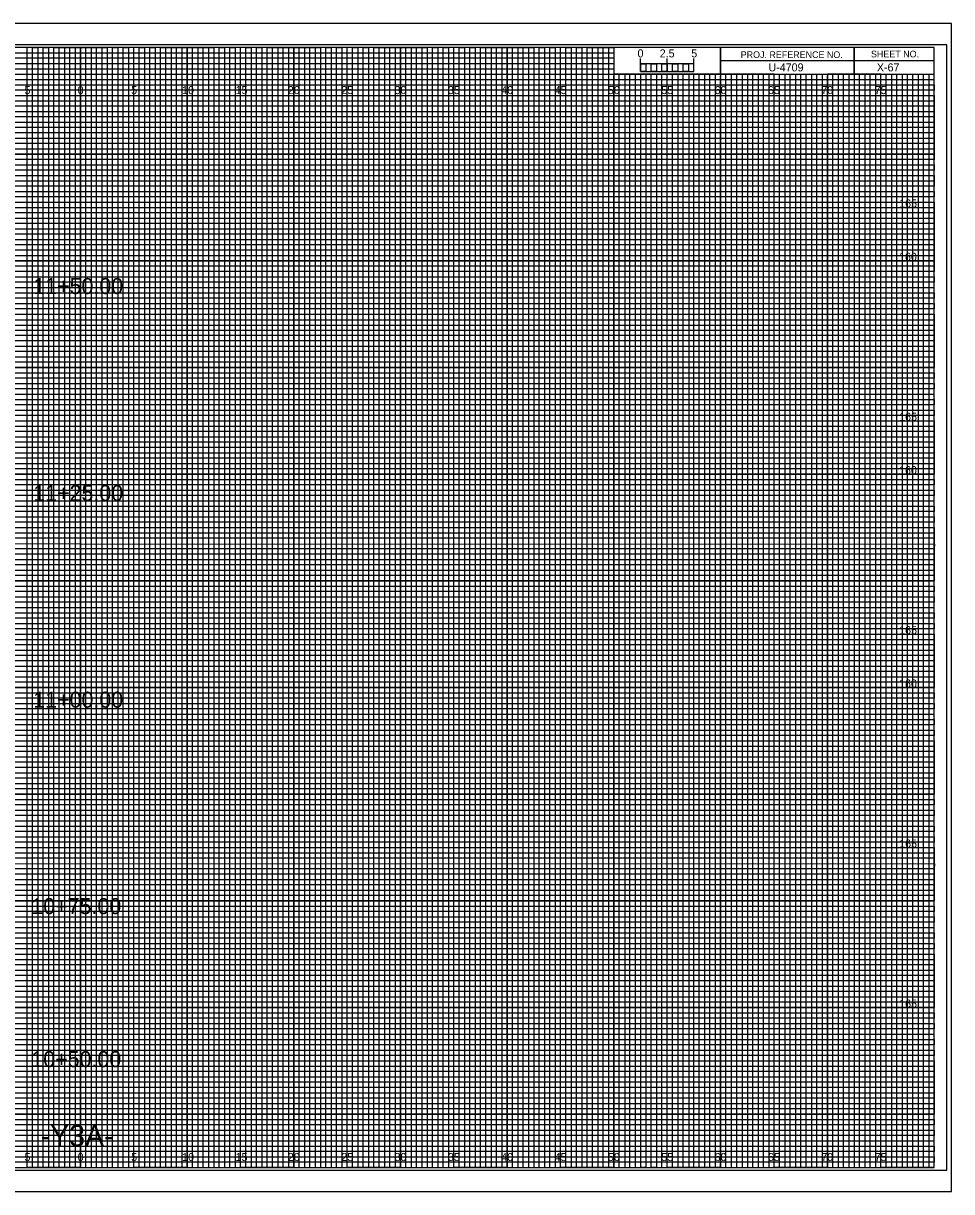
# Model space of a CAD drawing. Extents: x -7 to 162, y -2 to 107.
# Drawn here: x 74.6 to 161.7, y -2.3 to 107.3 of the extents above; entities that cross this region are included whole.
import ezdxf

# ---------------------------------------------------------------- set-up
doc = ezdxf.new("R2010")
doc.units = 0
for name, color, linetype in [('Prop CMT Slope Grass', 7, 'Continuous'), ('Prop XS Alignment Label', 7, 'Continuous'), ('Prop XS Bar Scale Labels', 7, 'Continuous'), ('Prop XS Earthwork Shape', 7, 'Continuous'), ('Prop XS Elevation Labels', 7, 'Continuous'), ('Prop XS Hydro Elevations', 7, 'Continuous'), ('Prop XS Project Number', 7, 'Continuous'), ('Prop XS SE Text', 7, 'Continuous'), ('Prop XS Sheet Number', 7, 'Continuous'), ('Prop XS Side Slope Text', 7, 'Continuous'), ('Prop XS Station Labels', 7, 'Continuous'), ('Sheet Cross Section Grid Minor 2 CELL', 7, 'Continuous'), ('Sheet Cross Section Scale CELL', 7, 'Continuous'), ('Sheet Cutting Line CELL', 7, 'Continuous'), ('Sheet DOT Grid CELL', 7, 'Continuous'), ('Sheet Plot Border Inside CELL', 7, 'Continuous'), ('Sheet Plot Border Outside CELL', 7, 'Continuous')]:
    doc.layers.add(name, color=color, linetype=linetype)

msp = doc.modelspace()

# ---------------------------------------------------------------- linework, layer by layer
at = {"layer": 'Prop XS Earthwork Shape'}
for p, q in [((152.5, 105), (152.5, 102.5)), ((152.5, 102.5), (152.5, 105)), ((160, 103.75), (140, 103.75)), ((140, 103.75), (140, 102.5)), ((140, 102.5), (160, 102.5))]:
    msp.add_line(p, q, dxfattribs=at)
for points in [[(160, 105), (0, 105), (0, 0), (160, 0)], [(140, 105), (130, 105), (130, 102.52), (140, 102.52)], [(160, 105), (140, 105), (140, 102.5), (160, 102.5)]]:
    msp.add_lwpolyline(points, close=True, dxfattribs=at)
at = {"layer": 'Prop XS Hydro Elevations'}
for p, q in [((0, 104.5), (130, 104.5)), ((130, 104.5), (130, 103.99)), ((130, 103.99), (0, 103.99)), ((0, 103.5), (130, 103.5)), ((130, 102.95), (0, 102.95)), ((130, 103.5), (130, 102.95)), ((0, 102), (160, 102))]:
    msp.add_line(p, q, dxfattribs=at)
for points in [[(0, 101.5), (135, 101.5), (160, 101.5), (160, 101), (0, 101)], [(0, 100.5), (160, 100.5), (160, 99.5), (0, 99.5)], [(0, 99), (160, 99), (160, 98.5), (0, 98.49)], [(0, 98), (160, 98), (160, 97), (0, 97)], [(0, 96.5), (160, 96.5), (160, 96), (0, 96)], [(0, 95.5), (160, 95.5), (160, 94.5), (0, 94.5)], [(0, 94), (160, 94), (160, 93.5), (0, 93.5)], [(0, 93), (160, 93), (160, 92), (0, 92)], [(0, 91.5), (160, 91.5), (160, 91), (0, 91)], [(0, 90.5), (160, 90.5), (160, 89.5), (0, 89.5)], [(0, 89), (160, 89), (160, 88.5), (0, 88.5)], [(0, 88), (160, 88), (160, 86.98), (160, 86.5), (160, 86), (0, 86)], [(0, 87), (160, 87), (160, 86.5), (0, 86.5)], [(0, 85.5), (160, 85.5), (160, 84.5), (0, 84.52)], [(0, 84.52), (160, 84.5), (160, 84), (0, 84)], [(0, 83.5), (160, 83.5), (160, 83), (0, 83)], [(0, 82), (160, 82), (160, 81.5), (0, 81.5)], [(0, 81), (160, 81), (160, 80.5), (0, 80.5)], [(-0.04, 79.45), (160, 79.45), (160, 78.94), (-0.04, 78.94)], [(0, 78.5), (160, 78.5), (160, 78), (0, 78)], [(0, 77), (160, 77), (160, 76.5), (0, 76.5)], [(0, 76), (160, 76), (160, 75.5), (0, 75.5)], [(0, 74.5), (160, 74.5), (160, 74), (0, 74)], [(0, 73.5), (160, 73.5), (160, 73), (0, 73)], [(0, 72), (160, 72), (160, 71.5), (0, 71.5)], [(0, 71), (160, 71), (160, 70.5), (0, 70.5)], [(0, 69.5), (160, 69.5), (160, 68.99), (0, 69)], [(0, 68.5), (160, 68.5), (160, 68), (0, 68)], [(0, 67), (160, 67), (160, 66.5), (0, 66.5)], [(0, 66), (160, 66), (160, 65.5), (0, 65.5)], [(0, 64.5), (160, 64.5), (160, 64), (0, 64)], [(0, 63.5), (160, 63.5), (160, 63), (0, 63)], [(0, 62), (160, 62), (160, 61.5), (0, 61.5)], [(0, 61), (160, 61), (160, 60.5), (0, 60.5)], [(0, 59.5), (160, 59.5), (160, 59), (0, 59)], [(0, 58.5), (160.03, 58.45), (160, 58), (0, 58)], [(0, 57), (160, 57), (160, 56.5), (0, 56.5)], [(0, 56), (160, 56), (160, 55.5), (0, 55.5)], [(0, 54.5), (160, 54.5), (160, 54), (0, 54)], [(0, 53.5), (160, 53.5), (160, 53), (0, 53)], [(0, 52), (160, 52), (160, 51.5), (0, 51.5)], [(0, 51), (160, 51), (160, 50.5), (0, 50.5)], [(0, 49.5), (160, 49.5), (160, 49), (0, 49)], [(0, 48.5), (160, 48.5), (160, 48), (0, 48)], [(0, 47), (160, 47), (160, 46.5), (0, 46.5)], [(0, 46), (160, 46), (160, 45.5), (0, 45.5)], [(0, 44.5), (160, 44.5), (160, 44), (0, 44)], [(0, 43.5), (160, 43.5), (160, 43), (0, 43)], [(0, 42), (160, 42), (160, 41.5), (0, 41.5)], [(0, 41), (160, 41), (160, 40.5), (0, 40.5)], [(0, 39.5), (160, 39.5), (160, 38.99), (0, 39)], [(0, 38.5), (160, 38.5), (160, 38), (0, 38)], [(0, 37), (160, 37), (160, 36.5), (0, 36.5)], [(0, 36), (160, 36), (160, 35.5), (0, 35.5)], [(0, 34.5), (160, 34.5), (160, 34), (0, 34)], [(0, 33.5), (160, 33.5), (160, 33), (0, 33)], [(0, 32), (160, 32), (160, 31.5), (0, 31.5)], [(0, 31), (160, 31), (160, 30.5), (0, 30.5)], [(0, 29.5), (160, 29.5), (160, 29), (0, 29)], [(0, 28.5), (160.03, 28.46), (160, 28), (0, 28)], [(0, 27), (160, 27), (160, 26.5), (0, 26.5)], [(0, 26), (160, 26), (160, 25.5), (0, 25.5)], [(0, 24.5), (160, 24.5), (160, 24), (0, 24)], [(0, 23.5), (160, 23.5), (160, 23), (0, 23)], [(0, 22), (160, 22), (160, 21.5), (0, 21.5)], [(0, 21), (160, 21), (160, 20.5), (0, 20.5)], [(0, 19.5), (160, 19.5), (160, 19), (0, 19)], [(0, 18.5), (160, 18.5), (160, 18), (0, 18)], [(0, 17), (160, 17), (160, 16.5), (0, 16.5)], [(0, 16), (160, 16), (160, 15.5), (0, 15.5)], [(0, 14.5), (160, 14.5), (160, 14), (0, 14)], [(0, 13.5), (160, 13.5), (160, 13), (0, 13)], [(0, 12), (160, 12), (160, 11.5), (0, 11.5)], [(0, 11), (160, 11), (160, 10.5), (0, 10.5)], [(0, 9.5), (160, 9.5), (160, 9), (0, 9)], [(0, 8.5), (160, 8.5), (160, 8), (0, 8)], [(0, 7), (160, 7), (160, 6.5), (0, 6.5)], [(0, 6), (160, 6), (160, 5.5), (0, 5.5)], [(0, 4.5), (160, 4.5), (160, 4), (0, 4)], [(0, 3.5), (160, 3.5), (160, 3), (0, 3)], [(0, 2), (160, 2), (160, 1.5), (0, 1.5)], [(0, 1), (160, 1), (160, 0.5), (0, 0.5)]]:
    msp.add_lwpolyline(points, dxfattribs=at)
at = {"layer": 'Prop XS SE Text'}
for p, q in [((75, 105), (70, 105)), ((75, 0), (75, 105)), ((85, 105), (80, 105)), ((80, 105), (80, 0)), ((85, 0), (85, 105)), ((95, 105), (90, 105)), ((90, 105), (90, 0)), ((95, 0), (95, 105)), ((105, 105), (100, 105)), ((100, 105), (100, 0)), ((105, 0), (105, 105)), ((115, 105), (110, 105)), ((110, 105), (110, 0)), ((115, 0), (115, 105)), ((125, 105), (120, 105)), ((120, 105), (120, 0)), ((125, 0), (125, 105)), ((130, 105), (130, 0)), ((135, 0), (135, 102.5)), ((145, 102.5), (140, 102.5)), ((140, 102.5), (140, 0)), ((145, 0), (145, 102.5)), ((155, 102.5), (150, 102.5)), ((150, 102.5), (150, 0)), ((155, 0), (155, 102.5)), ((80, 0), (75, 0)), ((90, 0), (85, 0)), ((100, 0), (95, 0)), ((110, 0), (105, 0)), ((120, 0), (115, 0)), ((130, 0), (125, 0)), ((140, 0), (135, 0)), ((150, 0), (145, 0)), ((160, 0), (155, 0)), ((160, 0), (160, 0))]:
    msp.add_line(p, q, dxfattribs=at)
for points in [[(0, 100), (160, 100), (160, 95), (0, 95)], [(0, 90), (160, 90), (160, 85), (0, 85)], [(0, 80), (160, 80), (160, 75), (0, 75)], [(0, 70), (160, 70), (160, 65), (0, 65)], [(0, 60), (160, 60), (160, 55), (0, 55)], [(0, 50), (160, 50), (160, 45), (0, 45)], [(0, 40), (160, 40), (160, 35), (0, 35)], [(0, 30), (160, 30), (160, 25), (0, 25)], [(0, 20), (160, 20), (160, 15), (0, 15)], [(0, 10), (160, 10), (160, 5), (0, 5)]]:
    msp.add_lwpolyline(points, dxfattribs=at)
at = {"layer": 'Prop XS Side Slope Text'}
for points in [[(72.5, 0), (77.5, 0), (77.5, 105), (82.5, 105), (82.5, 0), (87.5, 0), (87.5, 105), (92.5, 105), (92.5, 0), (97.5, 0), (97.5, 105), (102.5, 105), (102.5, 0), (107.5, 0), (107.5, 105), (112.5, 105), (112.5, 0), (117.5, 0), (117.5, 105), (122.5, 105), (122.5, 0), (127.5, 0), (127.5, 105), (129.97, 105), (130, 105), (130, 102.5), (132.5, 102.5), (132.5, 0), (137.5, 0), (137.5, 102.5), (142.5, 102.5), (142.5, 0), (147.5, 0), (147.5, 102.5), (152.5, 102.5), (152.5, 0), (157.5, 0), (157.5, 102.5)], [(0, 102.5), (137.5, 102.5)], [(0, 92.5), (160, 92.5), (160, 97.5), (0, 97.5)], [(0, 82.5), (160, 82.5), (160, 87.5), (0, 87.5)], [(0, 72.5), (160, 72.5), (160, 77.5), (0, 77.5)], [(0, 62.5), (160, 62.5), (160, 67.5), (0, 67.5)], [(0, 52.5), (160, 52.5), (160, 57.5), (0, 57.5)], [(0, 42.5), (160, 42.5), (160, 47.5), (0, 47.5)], [(0, 32.5), (160, 32.5), (160, 37.5), (0, 37.5)], [(0, 22.5), (160, 22.5), (160, 27.5), (0, 27.5)], [(0, 12.5), (160, 12.5), (160, 17.5), (0, 17.5)], [(0, 2.5), (160, 2.5), (160, 7.5), (0, 7.5)]]:
    msp.add_lwpolyline(points, dxfattribs=at)
at = {"layer": 'Sheet Cross Section Grid Minor 2 CELL'}
for p, q in [((133.5, 102.5), (133, 102.5)), ((133, 102.5), (133, 0)), ((133.5, 0), (133.5, 102.5)), ((134.5, 102.5), (134, 102.5)), ((134, 102.5), (134, 0)), ((134.5, 0), (134.5, 102.5)), ((133, 0), (132.5, 0)), ((134, 0), (133.5, 0))]:
    msp.add_line(p, q, dxfattribs=at)
for points in [[(75, 0), (75.5, 0), (75.5, 105), (76, 105), (76, 0)], [(76, 0), (76.5, 0), (76.5, 105), (77, 105), (77, 0)], [(77.5, 0), (78, 0), (78, 105), (78.5, 105), (78.5, 0)], [(78.5, 0), (79, 0), (79, 105), (79.5, 105), (79.5, 0)], [(80, 0), (80.5, 0), (80.5, 105), (81, 105), (81, 0)], [(81, 0), (81.5, 0), (81.5, 105), (82, 105), (82, 0)], [(82.5, 0), (83, 0), (83, 105), (83.5, 105), (83.5, 0)], [(83.5, 0), (84, 0), (84, 105), (84.5, 105), (84.5, 0)], [(85, 0), (85.5, 0), (85.5, 105), (86, 105), (86, 0)], [(86, 0), (86.5, 0), (86.5, 105), (87, 105), (87, 0)], [(87.5, 0), (88, 0), (88, 105), (88.5, 105), (88.5, 0)], [(88.5, 0), (89, 0), (89, 105), (89.5, 105), (89.5, 0)], [(90, 0), (90.5, 0), (90.5, 105), (91, 105), (91, 0)], [(91, 0), (91.5, 0), (91.5, 105), (92, 105), (92, 0)], [(92.5, 0), (93, 0), (93, 105), (93.5, 105), (93.5, 0)], [(93.5, 0), (94, 0), (94, 105), (94.5, 105), (94.5, 0)], [(95, 0), (95.5, 0), (95.5, 105), (96, 105), (96, 0)], [(96, 0), (96.5, 0), (96.5, 105), (97, 105), (97, 0)], [(97.5, 0), (98, 0), (98, 105), (98.5, 105), (98.5, 0)], [(98.5, 0), (99, 0), (99, 105), (99.5, 105), (99.5, 0)], [(100, 0), (100.5, 0), (100.5, 105), (101, 105), (101, 0)], [(101, 0), (101.5, 0), (101.5, 105), (102, 105), (102, 0)], [(102.5, 0), (103, 0), (103, 105), (103.5, 105), (103.5, 0)], [(103.5, 0), (104, 0), (104, 105), (104.5, 105), (104.5, 0)], [(105, 0), (105.5, 0), (105.5, 105), (106, 105), (106, 0)], [(106, 0), (106.5, 0), (106.5, 105), (107, 105), (107, 0)], [(107.5, 0), (108, 0), (108, 105), (108.5, 105), (108.5, 0)], [(108.5, 0), (109, 0), (109, 105), (109.5, 105), (109.5, 0)], [(110, 0), (110.5, 0), (110.5, 105), (111, 105), (111, 0)], [(111, 0), (111.5, 0), (111.5, 105), (112, 105), (112, 0)], [(112.5, 0), (113, 0), (113, 105), (113.5, 105), (113.5, 0)], [(113.5, 0), (114, 0), (114, 105), (114.5, 105), (114.5, 0)], [(115, 0), (115.5, 0), (115.5, 105), (116, 105), (116, 0)], [(116, 0), (116.5, 0), (116.5, 105), (117, 105), (117, 0)], [(117.5, 0), (118, 0), (118, 105), (118.5, 105), (118.5, 0)], [(118.5, 0), (119, 0), (119, 105), (119.5, 105), (119.5, 0)], [(120, 0), (120.5, 0), (120.5, 105), (121, 105), (121, 0)], [(121, 0), (121.5, 0), (121.5, 105), (122, 105), (122, 0)], [(122.5, 0), (123, 0), (123, 105), (123.5, 105), (123.5, 0)], [(123.5, 0), (124, 0), (124, 105), (124.5, 105), (124.5, 0)], [(125, 0), (125.5, 0), (125.5, 105), (126, 105), (126, 0)], [(126, 0), (126.5, 0), (126.5, 105), (127, 105), (127, 0)], [(127.5, 0), (128, 0), (128, 105), (128.5, 105), (128.5, 0)], [(128.5, 0), (129, 0), (129, 105), (129.5, 105), (129.5, 0)], [(130, 0), (130.5, 0), (130.5, 102.5), (131.01, 102.5), (131.01, 0)], [(131, 0), (131.5, 0), (131.5, 102.5), (132, 102.5), (132, 0)], [(135, 0), (135.49, 0), (135.49, 102.5), (136, 102.5), (136, 0)], [(136, 0), (136.5, 0), (136.5, 102.5), (137.03, 102.5), (137.03, 0)], [(137.5, 0), (138, 0), (138, 102.5), (138.5, 102.5), (138.5, 0)], [(138.5, 0), (139, 0), (139, 102.5), (139.5, 102.5), (139.5, 0)], [(140, 0), (140.5, 0), (140.5, 102.5), (141, 102.5), (141, 0)], [(141, 0), (141.5, 0), (141.5, 102.5), (142, 102.5), (142, 0)], [(142.5, 0), (143, 0), (143, 102.5), (143.5, 102.5), (143.5, 0)], [(143.5, 0), (144, 0), (144, 102.5), (144.5, 102.5), (144.5, 0)], [(145, 0), (145.5, 0), (145.5, 102.5), (146, 102.5), (146, 0)], [(146, 0), (146.5, 0), (146.5, 102.5), (147, 102.5), (147, 0)], [(147.5, 0), (148, 0), (148, 102.5), (148.5, 102.5), (148.5, 0)], [(148.5, 0), (149, 0), (149, 102.5), (149.5, 102.5), (149.5, 0)], [(150, 0), (150.5, 0), (150.5, 102.5), (151, 102.5), (151, 0)], [(151, 0), (151.5, 0), (151.5, 102.5), (152, 102.5), (152, 0)], [(152.5, 0), (153, 0), (153, 102.5), (153.5, 102.5), (153.5, 0)], [(153.5, 0), (154, 0), (154, 102.5), (154.5, 102.5), (154.5, 0)], [(155, 0), (155.5, 0), (155.5, 102.5), (156, 102.5), (156, 0)], [(156, 0), (156.5, 0), (156.5, 102.5), (157, 102.5), (157, 0)], [(157.5, 0), (158, 0), (158, 102.5), (158.5, 102.5), (158.5, 0)], [(158.5, 0), (159, 0), (159, 102.5), (159.5, 102.5), (159.5, 0)]]:
    msp.add_lwpolyline(points, dxfattribs=at)
at = {"layer": 'Sheet Cross Section Scale CELL'}
for p, q in [((132.5, 102.75), (132.5, 103.95)), ((132.5, 103.45), (132.5, 103.95)), ((135, 102.75), (135, 103.95)), ((137.5, 102.75), (137.5, 103.95)), ((137.5, 103.45), (137.5, 103.95))]:
    msp.add_line(p, q, dxfattribs=at)
for points in [[(137.5, 103.45), (132.5, 103.45), (132.5, 102.75), (137.5, 102.75)], [(132.5, 103.45), (133, 103.45), (133, 102.75), (132.5, 102.75)], [(133.5, 103.45), (134, 103.45), (134, 102.75), (133.5, 102.75)], [(134.5, 103.45), (135, 103.45), (135, 102.75), (134.5, 102.75)], [(135.5, 103.45), (136, 103.45), (136, 102.75), (135.5, 102.75)], [(136.5, 103.45), (137, 103.45), (137, 102.75), (136.5, 102.75)]]:
    msp.add_lwpolyline(points, close=True, dxfattribs=at)
at = {"layer": 'Sheet Cutting Line CELL'}
for p, q in [((161.65, 107.25), (-6.7, 107.25)), ((-6.7, -2.25), (161.65, -2.25))]:
    msp.add_line(p, q, dxfattribs=at)
at = {"layer": 'Sheet DOT Grid CELL'}
for p, q in [((75, 0), (75, 105)), ((80, 0), (80, 105)), ((85, 0), (85, 105)), ((90, 0), (90, 105)), ((95, 0), (95, 105)), ((100, 0), (100, 105)), ((105, 0), (105, 105)), ((110, 0), (110, 105)), ((115, 0), (115, 105)), ((120, 0), (120, 105)), ((125, 0), (125, 105)), ((130, 0), (130, 102.34)), ((135, 0), (135, 102.34)), ((140, 0), (140, 102.34)), ((145, 0), (145, 102.34)), ((150, 0), (150, 102.34)), ((155, 0), (155, 102.34)), ((0, 100), (160, 100)), ((0, 95), (160, 95)), ((0, 90), (160, 90)), ((0, 85), (160, 85)), ((0, 80), (160, 80)), ((0, 75), (160, 75)), ((0, 70), (160, 70)), ((0, 65), (160, 65)), ((0, 60), (160, 60)), ((0, 55), (160, 55)), ((0, 50), (160, 50)), ((0, 45), (160, 45)), ((0, 40), (160, 40)), ((0, 35), (160, 35)), ((0, 30), (160, 30)), ((0, 25), (160, 25)), ((0, 20), (160, 20)), ((0, 15), (160, 15)), ((0, 10), (160, 10)), ((0, 5), (160, 5))]:
    msp.add_line(p, q, dxfattribs=at)
at = {"layer": 'Sheet Plot Border Inside CELL'}
msp.add_lwpolyline([(-5.4, -0.25), (161.2, -0.25), (161.2, 105.25), (-5.4, 105.25)], close=True, dxfattribs=at)
at = {"layer": 'Sheet Plot Border Outside CELL'}
msp.add_lwpolyline([(-6.7, -2.25), (161.65, -2.25), (161.65, 107.25), (-6.7, 107.25)], close=True, dxfattribs=at)

# ---------------------------------------------------------------- texts
at = {"layer": 'Prop CMT Slope Grass'}
for s, p in [('5', (74.74, 100.62)), ('0', (79.73, 100.62)), ('0', (79.73, 100.62)), ('5', (84.74, 100.62)), ('10', (89.52, 100.62)), ('15', (94.53, 100.62)), ('20', (99.43, 100.62)), ('25', (104.44, 100.62)), ('30', (109.43, 100.62)), ('35', (114.44, 100.62)), ('40', (119.43, 100.62)), ('45', (124.44, 100.62)), ('50', (129.43, 100.62)), ('55', (134.44, 100.62)), ('60', (139.43, 100.62)), ('65', (144.44, 100.62)), ('70', (149.43, 100.62)), ('75', (154.44, 100.62)), ('5', (74.74, 0.62)), ('0', (79.73, 0.62)), ('0', (79.73, 0.62)), ('5', (84.74, 0.62)), ('10', (89.52, 0.62)), ('15', (94.53, 0.62)), ('20', (99.43, 0.62)), ('25', (104.44, 0.62)), ('30', (109.43, 0.62)), ('35', (114.44, 0.62)), ('40', (119.43, 0.62)), ('45', (124.44, 0.62)), ('50', (129.43, 0.62)), ('55', (134.44, 0.62)), ('60', (139.43, 0.62)), ('65', (144.44, 0.62)), ('70', (149.43, 0.62)), ('75', (154.44, 0.62))]:
    msp.add_text(s, height=0.75, dxfattribs=at).set_placement(p)
at = {"layer": 'Prop XS Alignment Label'}
msp.add_text('-Y3A-', height=2, dxfattribs=at).set_placement((76.26, 2))
at = {"layer": 'Prop XS Bar Scale Labels'}
for s, p in [('2.5', (134.29, 104.06)), ('5', (137.24, 104.06))]:
    msp.add_text(s, height=0.75, dxfattribs=at).set_placement(p)
at = {"layer": 'Prop XS Earthwork Shape'}
for s, p in [('PROJ. REFERENCE NO.', (141.88, 104)), ('SHEET NO.', (154.09, 104.06))]:
    msp.add_text(s, height=0.625, dxfattribs=at).set_placement(p)
at = {"layer": 'Prop XS Elevation Labels'}
for s, p in [('165', (156.73, 90)), ('160', (156.72, 85)), ('165', (156.73, 70)), ('160', (156.72, 65)), ('165', (156.73, 50)), ('160', (156.72, 45)), ('165', (156.73, 30)), ('165', (156.73, 15))]:
    msp.add_text(s, height=0.75, dxfattribs=at).set_placement(p)
at = {"layer": 'Prop XS Project Number'}
msp.add_text('U-4709', height=0.75, dxfattribs=at).set_placement((144.48, 102.75))
at = {"layer": 'Prop XS Sheet Number'}
msp.add_text('X-67', height=0.75, dxfattribs=at).set_placement((154.64, 102.75))
at = {"layer": 'Prop XS Station Labels'}
for s, p in [('11+50.00', (75.57, 81.88)), ('11+25.00', (75.57, 62.48)), ('11+00.00', (75.57, 43.11)), ('10+75.00', (75.39, 23.76)), ('10+50.00', (75.39, 9.42))]:
    msp.add_text(s, height=1.5, dxfattribs=at).set_placement(p)
at = {"layer": 'Sheet Cross Section Scale CELL'}
msp.add_text('0', height=0.75, dxfattribs=at).set_placement((132.21, 104.06))

doc.saveas('drawing.dxf')
